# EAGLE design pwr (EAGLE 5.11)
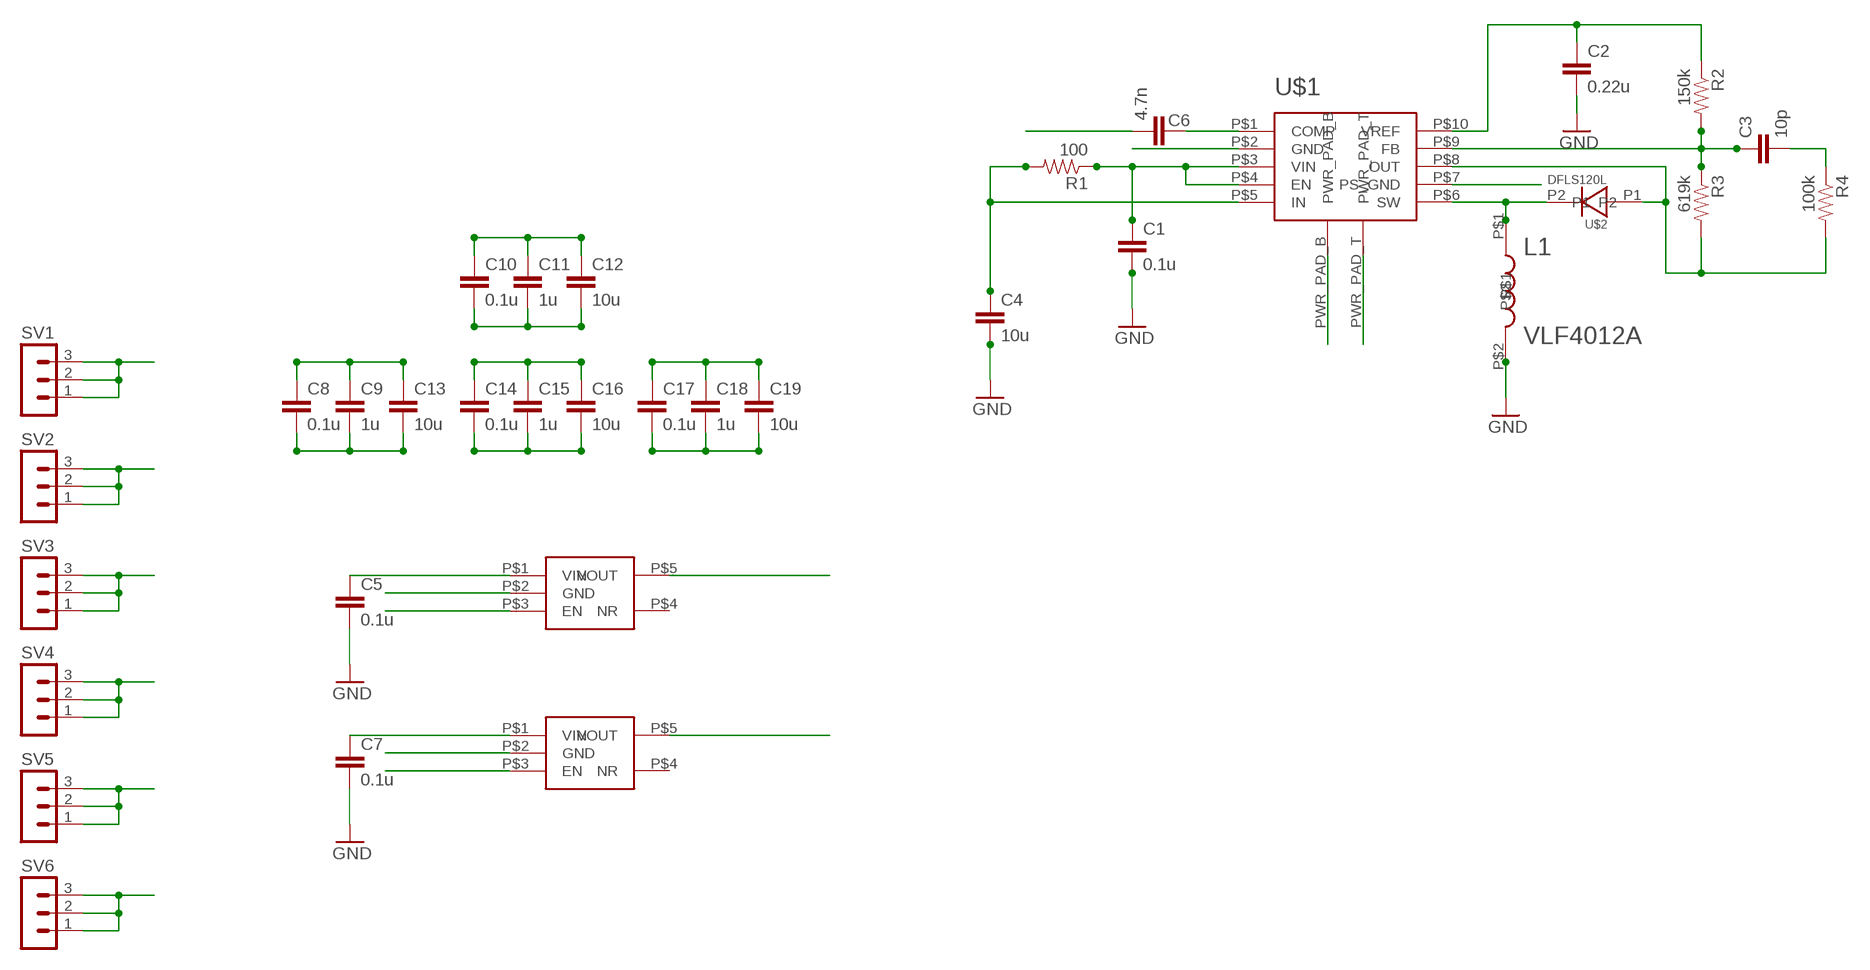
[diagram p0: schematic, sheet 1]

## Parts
C1  0.1u  CAP0603-CAP  [0603-CAP]
C2  0.22u  CAP0603-CAP  [0603-CAP]
C3  10p  CAP0603-CAP  [0603-CAP]
C4  10u  CAP0805  [0805]
C5  0.1u  CAP0603-CAP  [0603-CAP]
C6  4.7n  CAP0603-CAP  [0603-CAP]
C7  0.1u  CAP0603-CAP  [0603-CAP]
C8  0.1u  CAP0603-CAP  [0603-CAP]
C9  1u  CAP0603-CAP  [0603-CAP]
C10  0.1u  CAP0603-CAP  [0603-CAP]
C11  1u  CAP0603-CAP  [0603-CAP]
C12  10u  CAP0805  [0805]
C13  10u  CAP0805  [0805]
C14  0.1u  CAP0603-CAP  [0603-CAP]
C15  1u  CAP0603-CAP  [0603-CAP]
C16  10u  CAP0805  [0805]
C17  0.1u  CAP0603-CAP  [0603-CAP]
C18  1u  CAP0603-CAP  [0603-CAP]
C19  10u  CAP0805  [0805]
L1  VLF4012A  [VLF4012A]
R1  100  RESISTOR0603-RES  [0603-RES]
R2  150k  RESISTOR0603-RES  [0603-RES]
R3  619k  RESISTOR0603-RES  [0603-RES]
R4  100k  RESISTOR0603-RES  [0603-RES]
SV1  MA03-1  [MA03-1]
SV2  MA03-1  [MA03-1]
SV3  MA03-1  [MA03-1]
SV4  MA03-1  [MA03-1]
SV5  MA03-1  [MA03-1]
SV6  MA03-1  [MA03-1]
U1  REG102  [SOT-5]
U2  REG102  [SOT-5]
U$1  TPS63700  [SON10]
U$2  DFLS120L  [POWER_DI]

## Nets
GND: C1.2 C2.2 C4.2 C5.2 C6.2 C7.2 C8.2 C9.2 C10.2 C11.2 C12.2 C13.2 C14.2 C15.2 C16.2 C17.2 C18.2 C19.2 L1.P$2 SV2.1 SV2.2 SV2.3 U1.P$2(GND) U2.P$2(GND) U$1.P$2(GND) U$1.P$7(PS_GND) U$1.PWR_PAD_B U$1.PWR_PAD_T
N$1: C1.1 R1.1 U$1.P$3(VIN) U$1.P$4(EN)
N$3: C6.1 U$1.P$1(COMP)
N$4: L1.P$1 U$1.P$6(SW) U$2.P2
N$6: C3.1 R2.2 R3.1 U$1.P$9(FB)
N$8: C2.1 R2.1 U$1.P$10(VREF)
N$9: C3.2 R4.1
VIN: C4.1 C5.1 C7.1 C10.1 C11.1 C12.1 R1.2 SV1.1 SV1.2 SV1.3 SV6.1 SV6.2 SV6.3 U1.P$1(VIN) U1.P$3(EN) U2.P$1(VIN) U2.P$3(EN) U$1.P$5(IN)
VOUT2.85: C17.1 C18.1 C19.1 SV5.1 SV5.2 SV5.3 U1.P$5(VOUT)
VOUT3.3: C14.1 C15.1 C16.1 SV4.1 SV4.2 SV4.3 U2.P$5(VOUT)
VOUT-5: C8.1 C9.1 C13.1 R3.2 R4.2 SV3.1 SV3.2 SV3.3 U$1.P$8(OUT) U$2.P1
Unconnected: U1.P$4(NR) U2.P$4(NR)

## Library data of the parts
C1-C19 = SparkFun:CAP: Capacitor
L1 = sam:VLF4012A
R1-R4 = SparkFun:RESISTOR: Resistor
SV1-SV6 = con-lstb:MA03-1: PIN HEADER; OC_FARNELL: unknown; OC_NEWARK: unknown
U1 U2 = sam:REG102
U$1 = sam:TPS63700
U$2 = sam:DFLS120L

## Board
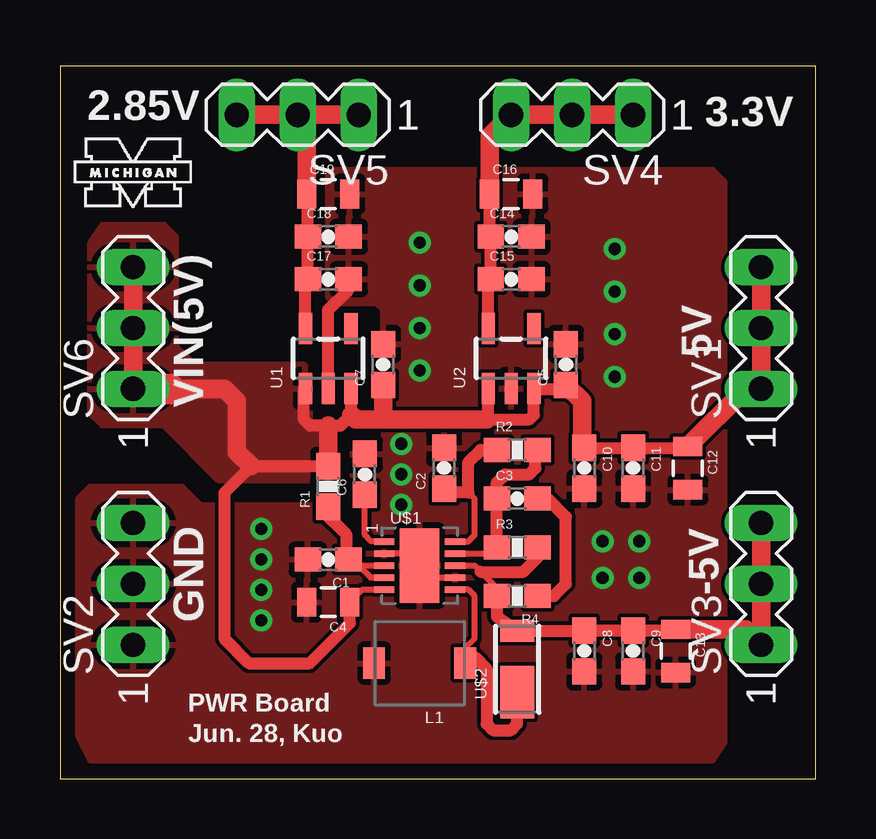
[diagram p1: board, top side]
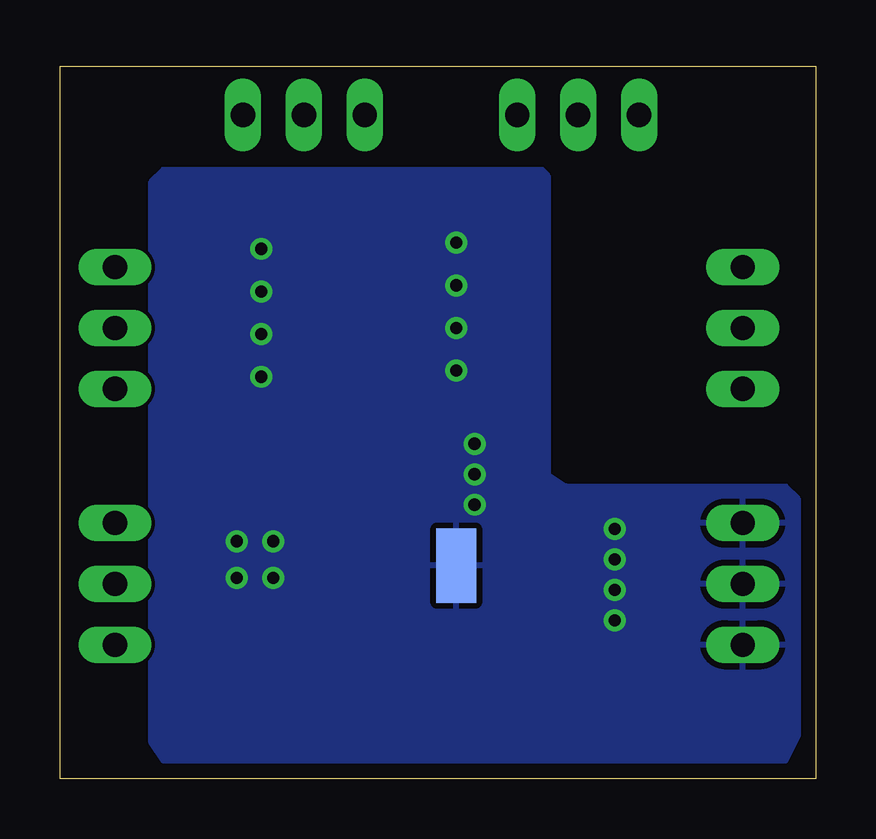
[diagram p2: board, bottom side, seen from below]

Size 31.5 x 29.72 mm. Coordinates in mm from the lower left corner, seen from the top.
Outline: 0,0 31.5,0 31.5,29.72 0,29.72 0,0
Copper layers (1*16): Top 0.0178mm / dielectric 1.4986mm / Bottom 0.0178mm
Design rules "SSC-EAGLE-2Lyr_v1.0.0.3": minimum track width 6mil, minimum drill 14mil, track to track 6mil, track to pad 6mil, pad to pad 6mil, via to via 6mil, smd to smd 6mil, copper to edge 20mil, drill to drill 16mil, minimum pad ring 8mil, minimum via ring 8mil, stop-mask expansion 3mil, vias tented up to drill 0mil, thermal gap 10mil

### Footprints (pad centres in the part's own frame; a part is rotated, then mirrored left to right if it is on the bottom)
0603-CAP = smd 1.1 x 1: 1 -0.85,0; 2 0.85,0
0805 = smd 0.8 x 1.2: 1 -0.9,0; 2 0.9,0
VLF4012A = smd 0.9 x 1.3: P$1 -1.9,0; P$2 1.9,0
0603-RES = smd 1.1 x 1: 1 -0.85,0; 2 0.85,0
MA03-1 = drill 1.016 long: 1 -2.54,0; 2 0,0; 3 2.54,0
SOT-5 = smd 1.3 x 0.55: P$1 -1.25,0.95; P$2 -1.25,0; P$3 -1.25,-0.95; P$4 1.25,-0.95; P$5 1.25,0.95
SON10 = smd 0.28 x 0.85: P$1 -1,-1.475; P$2 -0.5,-1.475; P$3 0,-1.475; P$4 0.5,-1.475; P$5 1,-1.475; P$6 1,1.475; P$7 0.5,1.475; P$8 0,1.475; P$9 -0.5,1.475; P$10 -1,1.475 | smd 3.1 x 1.65 bottom: PWR_PAD_B 0,0 | smd 3.1 x 1.65: PWR_PAD_T 0,0
POWER_DI = smd 0.9 x 1.4: P1 1.6,0 | smd 2.2 x 1.4: P2 -0.95,0

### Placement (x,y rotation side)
C1  11.18,9.14 180 top
C2  16,12.95 90 top
C3  19.05,11.68 0 top
C4  11.18,7.37 180 top
C5  21.08,17.27 90 top
C6  12.7,12.7 90 top
C7  13.46,17.27 90 top
C8  21.84,5.33 270 top
C9  23.88,5.33 270 top
C10  21.84,12.95 270 top
C11  23.88,12.95 270 top
C12  26.16,12.95 270 top
C13  25.65,5.33 270 top
C14  18.8,22.61 0 top
C15  18.8,20.83 0 top
C16  18.8,24.38 0 top
C17  11.18,20.83 0 top
C18  11.18,22.61 0 top
C19  11.18,24.38 0 top
L1  14.99,4.83 180 top
R1  11.18,12.19 90 top
R2  19.05,13.72 0 top
R3  19.05,9.65 0 top
R4  19.05,7.62 180 top
SV1  29.21,18.8 90 top
SV2  3.05,8.13 90 top
SV3  29.21,8.13 90 top
SV4  21.34,27.69 180 top
SV5  9.91,27.69 180 top
SV6  3.05,18.8 90 top
U1  11.18,17.53 90 top
U2  18.8,17.53 90 top
U$1  14.99,8.89 270 top
U$2  19.05,4.57 90 top
U$3  [UMICH]  0.51,23.62 0 top

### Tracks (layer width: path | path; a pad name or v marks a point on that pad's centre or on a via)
GND  (via drill 0.51)
  Top 0.254: U$1.P$2 14.49,9.39 U$1.PWR_PAD_T | U$1.P$7 14.99,8.39 14.99,8.38
  Top 0.508: U1.P$2 11.18,19.56 12.03,20.41 C17.2
  other vias: 14.22,13.97 14.22,12.7 14.22,11.43 14.99,17.02 14.99,20.57 14.99,22.35 14.99,18.8 23.11,18.54 23.11,20.32 23.11,22.1 23.11,16.76 24.13,9.91 22.61,9.91 22.61,8.38 24.13,8.38 8.38,10.41 8.38,9.14 8.38,7.87 8.38,6.6
  pour Top: 11.18,20.07 11.18,25.15 11.43,25.4 27.18,25.4 27.69,24.89 27.69,1.52 27.18,0.76 1.27,0.76 0.76,1.78 0.76,11.68 1.27,12.19 5.08,12.19 5.84,11.43 11.94,11.43 12.19,11.68 12.19,13.72 12.45,13.97 13.21,13.97 13.46,14.22 13.46,19.56 13.21,19.81 11.43,19.81
  pour Bottom: 11.18,25.15 11.18,12.7 10.41,12.19 1.27,12.19 0.76,11.68 0.76,1.78 1.27,0.76 27.18,0.76 27.69,1.52 27.69,24.89 27.18,25.4 11.43,25.4
N$1
  Top 0.254: 12.45,8.89 12.28,8.89 C1.1 | 12.45,8.89 U$1.P$3 | U$1.P$4 12.95,8.39 12.45,8.89
  Top 0.508: R1.1 10.92,11.18 11.94,10.16 11.94,9.23 C1.1
N$3
  Top 0.254: 13.22,9.89 U$1.P$1 13.49,9.91 12.95,9.91 12.7,10.16 C6.1
N$4
  Top 0.254: U$1.P$6 17,7.89 17.27,7.62 17.27,5.84 16.89,5.46 L1.P$1
  Top 0.508: L1.P$1 17.27,5.08 17.78,4.57 17.78,2.29 18.03,2.03 18.8,2.03 19.05,2.29 U$2.P2
N$6
  Top 0.254: U$1.P$9 17.94,9.39 R3.1
  Top 0.508: R3.1 C3.1 18.2,12.36 18.54,12.7 19.56,12.7 19.81,12.95 19.81,13.63 R2.2
N$8
  Top 0.254: U$1.P$10 17,9.89 17.27,10.16 17.27,11.68 17.02,11.94
  Top 0.508: R2.1 17.53,13.72 17.02,13.21 17.02,11.94 16.17,11.94 C2.1
N$9
  Top 0.508: C3.2 20.32,11.68 21.08,10.92 21.08,8.13 20.57,7.62 R4.1
VIN
  Top 0.254: U$1.P$5 12.6,7.89 C4.1
  Top 0.508: 12.15,16.26 U1.P$3 12.13,15.17 11.68,14.73 11.18,14.73 10.41,14.73 10.16,14.99 10.16,16.21 U1.P$1 | 21.76,13.89 C10.1 C11.1 26.11,13.8 C12.1 | U2.P$1 17.85,15.05 17.78,14.99 19.56,14.99 19.75,15.17 U2.P$3 19.77,16.26 20.92,16.26 C5.1 | R1.2 7.96,13.04 6.86,11.94 6.86,5.84 7.87,4.83 10.41,4.83 12.08,6.49 C4.1
  Top 0.762: SV1.3 SV1.2 SV1.1 28.56,16.26 C12.1 | 13.46,14.99 12.31,14.99 12.13,15.17 | 13.46,14.99 17.78,14.99 | 13.46,14.99 C7.1 | R1.2 11.18,14.73 | 4.57,16.26 6.86,16.26 7.37,15.75 7.37,13.64 7.96,13.04 | SV6.1 SV6.2 SV6.3 | 21.76,13.89 21.76,15.75 C5.1
  Top 1.27: 4.57,16.26 SV6.1
  pour Top: 1.27,22.35 1.78,23.11 4.32,23.11 4.83,22.61 4.83,18.03 5.59,17.27 10.16,17.27 10.41,17.02 10.41,14.99 10.67,14.48 11.18,14.48 11.43,14.22 11.43,12.7 11.18,12.45 6.6,12.45 4.32,14.73 1.78,14.73 1.27,15.24
VOUT2.85
  Top 0.508: U1.P$5 10.23,20.73 C17.1 C18.1 10.33,24.33 C19.1
  Top 0.762: C19.1 10.28,27.32 SV5.2 | SV5.2 SV5.3 | SV5.2 SV5.1
VOUT3.3
  Top 0.508: C16.1 17.9,22.66 C14.1 C15.1 17.85,20.73 U2.P$5
  Top 0.762: SV4.1 SV4.2 SV4.3 17.9,26.79 C16.1
VOUT-5
  Top 0.254: U$1.P$8 17.27,8.89 17.53,8.64 18.2,7.96 R4.2 | 19.9,9.23 R3.2
  Top 0.508: 19.9,9.23 19.3,8.64 17.53,8.64 | R4.2 18.2,6.77 U$2.P1 C8.1 C9.1 25.6,6.18 C13.1
  Top 0.762: SV3.3 SV3.2 SV3.1 28.56,6.23 C13.1

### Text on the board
tPlace: 2.85V | 3.3V | 5V | VIN(5V) | -5V | GND | PWR Board | Jun. 28, Kuo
